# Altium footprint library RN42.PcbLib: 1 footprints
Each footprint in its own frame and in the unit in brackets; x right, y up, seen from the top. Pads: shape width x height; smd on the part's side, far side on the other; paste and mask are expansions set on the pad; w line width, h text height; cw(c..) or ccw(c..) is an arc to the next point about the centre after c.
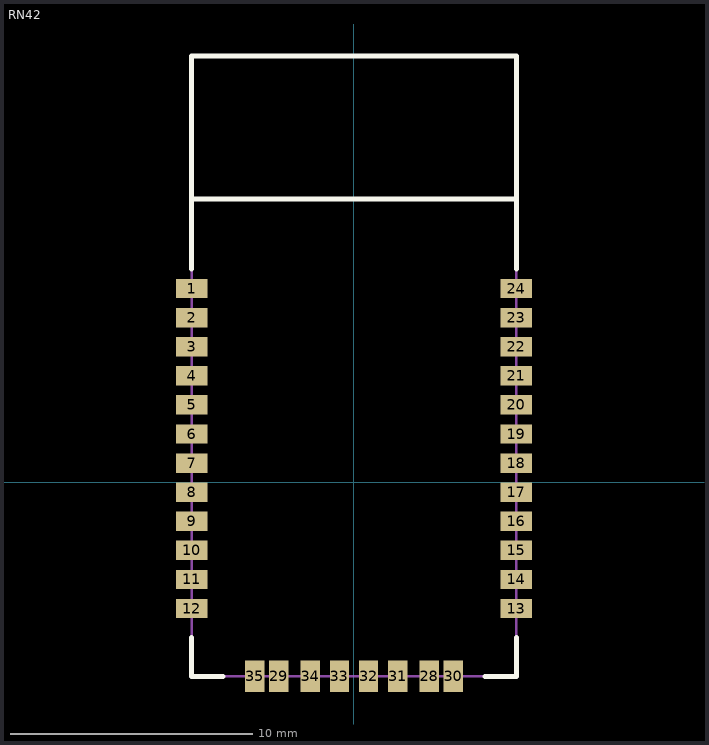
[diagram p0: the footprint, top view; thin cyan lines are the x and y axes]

## RN42 [mm] "RN42 Bluetooth Transciever"
pads (32):
  rect 1.3x0.8 smd: 1(-6.7,8) 2(-6.7,6.8) 3(-6.7,5.6) 4(-6.7,4.4) 5(-6.7,3.2) 6(-6.7,2) 7(-6.7,0.8) 8(-6.7,-0.4) 9(-6.7,-1.6) 10(-6.7,-2.8) 11(-6.7,-4) 12(-6.7,-5.2) 13(6.7,-5.2) 14(6.7,-4) 15(6.7,-2.8) 16(6.7,-1.6) 17(6.7,-0.4) 18(6.7,0.8) 19(6.7,2) 20(6.7,3.2) 21(6.7,4.4) 22(6.7,5.6) 23(6.7,6.8) 24(6.7,8)
  rect 0.8x1.3 smd: 28(3.1,-8) 29(-3.1,-8) 30(4.1,-8) 31(1.8,-8) 32(0.6,-8) 33(-0.6,-8) 34(-1.8,-8) 35(-4.1,-8)
Top Overlay:
  lines w0.203: -6.7,-6.4 -6.7,-8 -5.4,-8 ; -6.7,8.8 -6.7,17.6 3.7,17.6 6.7,17.6 6.7,8.8 ; -6.7,11.7 6.7,11.7 ; 5.4,-8 6.7,-8 6.7,-6.4
Mechanical 31:
  lines w0.102: -6.7,-8 6.7,-8 6.7,11.7 -6.7,11.7 -6.7,-8
  text ".Comment" at -4.625,5.2 h0.76
  text ".Designator" at -4.65,6.925 h0.76
3D body "User Library-RN42.step": height 2.12, standoff 0, extent -6.7,-8 6.7,17.8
